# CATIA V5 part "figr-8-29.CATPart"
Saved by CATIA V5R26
Part number: Part1
Bounding box of the stored display mesh (mm): x 37.5 to 207.5, y 10 to 85, z 0 to 113
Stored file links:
  D:\_Deepak\CATIA\CATIA V5-6R2016_Deepak\Resources\Part files\Partfiles\c08_catia_v5_6r2016_prt\figr-8-29.CATPart
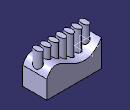
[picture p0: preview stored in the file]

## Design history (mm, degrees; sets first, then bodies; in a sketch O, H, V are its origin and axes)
Set1
  Plane1: type Offset, RefPlane xy-plane, Offset 113
Body1 (main body)
  Sketch1 on xy-plane, origin (0, 0, 0), H (1, 0, 0), V (0, 1, 0)
    line L1 (-37.5, 85) -> (37.5, 85)
    line L2 (37.5, 85) -> (37.5, -85)
    line L3 (37.5, -85) -> (-37.5, -85)
    line L4 (-37.5, -85) -> (-37.5, 85)
    axis line L5 (37.5, -85) -> (-37.5, 85)
    length L3 = 75
    length L2 = 170
    horizontal: L1 H, L3 H
    vertical: L2 V, L4 V
    midpoint: O L5
  Pad1: profile Sketch1, direction (0, 0, 1), length 83
  Sketch2 on face of Pad1, origin (37.5, 0, 0), H (0, 1, 0), V (0, 0, 1)
    spline S1 through (-85, 56.7422) (-58.5369, 80.0687) (-27.7952, 70.201) (85, 83)
    reference projected line E1 (85, 0) -> (85, 83) from edge [face of Pad1 | face of Pad1]
    reference projected line E2 (-85, 0) -> (-85, 83) from edge [face of Pad1 | face of Pad1]
    reference projected line E3 (-85, 83) -> (85, 83) from edge [face of Pad1 | face of Pad1]
    point P1 (85, 83)
    point P3 (-85, 56.7422)
    coincidence: P1 E1, P3 E2, P1 E3
  Pocket1: profile Sketch2, direction (-1, 0, 0), length 83
  Rotate1: ToTransfor Pocket1, Axis edge [face of Pad1 | face of Pad1], Angle 90
  Sketch3 on Plane1, origin (0, 0, 113), H (1, 0, 0), V (0, 1, 0)
    ellipse A1 centre (195.4286, 45.9861) semi-axes 14.9247, 8.8005 rotation 90
  Pad2: profile Sketch3, direction (0, 0, -1), up to face of Pocket1
  RectPattern1: of Pad2, direction 1 instances 7, spacing 24, along edge [face of Pad1 | face of Pad1]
